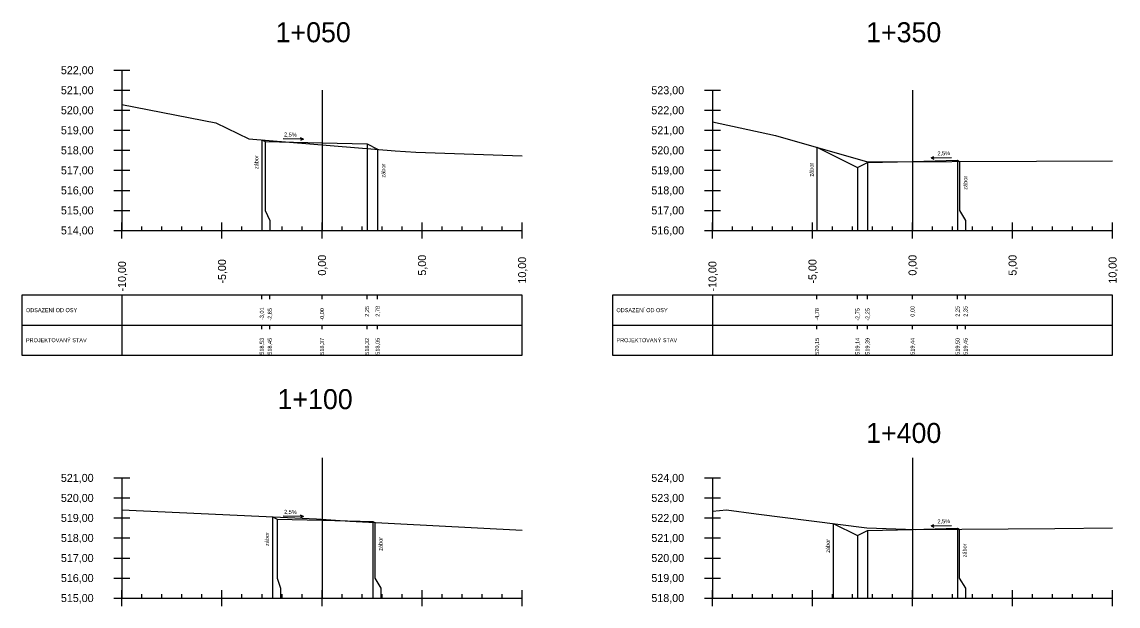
# Model space of a CAD drawing. Extents: x -631407 to -631215, y -1089700 to -1088598.
# Drawn here: x -631314.7 to -631259.9, y -1089386.7 to -1089357.5 of the extents above; entities that cross this region are included whole.
import ezdxf

# ---------------------------------------------------------------- set-up
doc = ezdxf.new("R2010")
doc.units = 0
for name, color, linetype in [('59', 7, 'Continuous'), ('NIVELETA_VYSKY', 7, 'Continuous'), ('REZ_BODY', 7, 'Continuous'), ('REZ_ODSTUPY', 7, 'Continuous'), ('REZ_POPIS', 7, 'Continuous'), ('REZ_RAMY', 7, 'Continuous'), ('REZ_STANICENI', 7, 'Continuous'), ('REZ_SVISLE', 7, 'Continuous'), ('REZ_TENKA', 7, 'Continuous'), ('REZ_TLUSTA', 7, 'Continuous'), ('TABULKA_POPIS', 7, 'Continuous'), ('TEREN', 7, 'Continuous'), ('zábor', 7, 'Continuous')]:
    doc.layers.add(name, color=color, linetype=linetype)

msp = doc.modelspace()

# ---------------------------------------------------------------- linework, layer by layer
at = {"layer": '59'}
for p, q in [((-631310.116, -1089359.911), (-631309.316, -1089359.911)), ((-631309.716, -1089359.911), (-631309.716, -1089367.911)), ((-631310.116, -1089360.911), (-631309.316, -1089360.911)), ((-631280.602, -1089360.911), (-631279.802, -1089360.911)), ((-631280.202, -1089360.911), (-631280.202, -1089367.911)), ((-631310.116, -1089361.911), (-631309.316, -1089361.911)), ((-631280.602, -1089361.911), (-631279.802, -1089361.911)), ((-631310.116, -1089362.911), (-631309.316, -1089362.911)), ((-631280.602, -1089362.911), (-631279.802, -1089362.911)), ((-631310.116, -1089363.911), (-631309.316, -1089363.911)), ((-631280.602, -1089363.911), (-631279.802, -1089363.911)), ((-631310.116, -1089364.911), (-631309.316, -1089364.911)), ((-631280.602, -1089364.911), (-631279.802, -1089364.911)), ((-631310.116, -1089365.911), (-631309.316, -1089365.911)), ((-631280.602, -1089365.911), (-631279.802, -1089365.911)), ((-631310.116, -1089366.911), (-631309.316, -1089366.911)), ((-631280.602, -1089366.911), (-631279.802, -1089366.911)), ((-631310.116, -1089367.911), (-631309.316, -1089367.911)), ((-631280.602, -1089367.911), (-631279.802, -1089367.911)), ((-631310.116, -1089380.273), (-631309.316, -1089380.273)), ((-631309.716, -1089380.273), (-631309.716, -1089386.273)), ((-631280.602, -1089380.273), (-631279.802, -1089380.273)), ((-631280.202, -1089380.273), (-631280.202, -1089386.273)), ((-631310.116, -1089381.273), (-631309.316, -1089381.273)), ((-631280.602, -1089381.273), (-631279.802, -1089381.273)), ((-631310.116, -1089382.273), (-631309.316, -1089382.273)), ((-631280.602, -1089382.273), (-631279.802, -1089382.273)), ((-631310.116, -1089383.273), (-631309.316, -1089383.273)), ((-631280.602, -1089383.273), (-631279.802, -1089383.273)), ((-631310.116, -1089384.273), (-631309.316, -1089384.273)), ((-631280.602, -1089384.273), (-631279.802, -1089384.273)), ((-631310.116, -1089385.273), (-631309.316, -1089385.273)), ((-631280.602, -1089385.273), (-631279.802, -1089385.273)), ((-631310.116, -1089386.273), (-631309.316, -1089386.273)), ((-631280.602, -1089386.273), (-631279.802, -1089386.273))]:
    msp.add_line(p, q, dxfattribs=at)
at = {"layer": 'REZ_RAMY'}
for p, q in [((-631314.716, -1089371.145), (-631314.716, -1089374.145)), ((-631309.716, -1089371.145), (-631309.716, -1089374.145)), ((-631302.726, -1089371.345), (-631302.726, -1089371.145)), ((-631302.326, -1089371.345), (-631302.326, -1089371.145)), ((-631299.716, -1089371.345), (-631299.716, -1089371.145)), ((-631297.466, -1089371.345), (-631297.466, -1089371.145)), ((-631296.937, -1089371.345), (-631296.937, -1089371.145)), ((-631285.202, -1089371.145), (-631285.202, -1089374.145)), ((-631280.202, -1089371.145), (-631280.202, -1089374.145)), ((-631274.978, -1089371.345), (-631274.978, -1089371.145)), ((-631272.952, -1089371.345), (-631272.952, -1089371.145)), ((-631272.452, -1089371.345), (-631272.452, -1089371.145)), ((-631270.202, -1089371.345), (-631270.202, -1089371.145)), ((-631267.952, -1089371.345), (-631267.952, -1089371.145)), ((-631267.552, -1089371.345), (-631267.552, -1089371.145)), ((-631314.716, -1089372.645), (-631289.716, -1089372.645)), ((-631302.726, -1089372.845), (-631302.726, -1089372.645)), ((-631302.326, -1089372.845), (-631302.326, -1089372.645)), ((-631299.716, -1089372.845), (-631299.716, -1089372.645)), ((-631297.466, -1089372.845), (-631297.466, -1089372.645)), ((-631296.937, -1089372.845), (-631296.937, -1089372.645)), ((-631285.202, -1089372.645), (-631260.202, -1089372.645)), ((-631274.978, -1089372.845), (-631274.978, -1089372.645)), ((-631272.952, -1089372.845), (-631272.952, -1089372.645)), ((-631272.452, -1089372.845), (-631272.452, -1089372.645)), ((-631270.202, -1089372.845), (-631270.202, -1089372.645)), ((-631267.952, -1089372.845), (-631267.952, -1089372.645)), ((-631267.552, -1089372.845), (-631267.552, -1089372.645))]:
    msp.add_line(p, q, dxfattribs=at)
for points in [[(-631314.716, -1089371.145), (-631314.716, -1089374.145), (-631289.716, -1089374.145), (-631289.716, -1089371.145)], [(-631285.202, -1089371.145), (-631285.202, -1089374.145), (-631260.202, -1089374.145), (-631260.202, -1089371.145)]]:
    msp.add_lwpolyline(points, close=True, dxfattribs=at)
at = {"layer": 'REZ_SVISLE'}
for points in [[(-631302.726, -1089363.386), (-631302.726, -1089366.911), (-631302.726, -1089367.411), (-631302.726, -1089367.911)], [(-631302.566, -1089363.466), (-631302.566, -1089366.911), (-631302.326, -1089367.411), (-631302.326, -1089367.911)], [(-631299.716, -1089363.537), (-631299.716, -1089366.911), (-631299.716, -1089367.411), (-631299.716, -1089367.911)], [(-631297.466, -1089363.594), (-631297.466, -1089366.911), (-631297.466, -1089367.411), (-631297.466, -1089367.911)], [(-631274.978, -1089363.761), (-631274.978, -1089366.911), (-631274.978, -1089367.411), (-631274.978, -1089367.911)], [(-631296.937, -1089363.858), (-631296.937, -1089366.911), (-631296.937, -1089367.411), (-631296.937, -1089367.911)], [(-631272.952, -1089364.774), (-631272.952, -1089366.911), (-631272.952, -1089367.411), (-631272.952, -1089367.911)], [(-631272.452, -1089364.524), (-631272.452, -1089366.911), (-631272.452, -1089367.411), (-631272.452, -1089367.911)], [(-631270.202, -1089364.467), (-631270.202, -1089366.911), (-631270.202, -1089367.411), (-631270.202, -1089367.911)], [(-631267.952, -1089364.411), (-631267.952, -1089366.911), (-631267.952, -1089367.411), (-631267.952, -1089367.911)], [(-631267.849, -1089364.463), (-631267.849, -1089366.911), (-631267.552, -1089367.411), (-631267.552, -1089367.911)], [(-631302.196, -1089382.211), (-631302.196, -1089385.273), (-631302.196, -1089385.773), (-631302.196, -1089386.273)], [(-631301.966, -1089382.326), (-631301.966, -1089385.273), (-631301.796, -1089385.773), (-631301.796, -1089386.273)], [(-631299.716, -1089382.383), (-631299.716, -1089385.273), (-631299.716, -1089385.773), (-631299.716, -1089386.273)], [(-631297.173, -1089382.446), (-631297.173, -1089385.273), (-631297.173, -1089385.773), (-631297.173, -1089386.273)], [(-631297.074, -1089382.496), (-631297.074, -1089385.273), (-631296.773, -1089385.773), (-631296.773, -1089386.273)], [(-631274.164, -1089382.546), (-631274.164, -1089385.273), (-631274.164, -1089385.773), (-631274.164, -1089386.273)], [(-631272.452, -1089382.903), (-631272.452, -1089385.273), (-631272.452, -1089385.773), (-631272.452, -1089386.273)], [(-631270.202, -1089382.846), (-631270.202, -1089385.273), (-631270.202, -1089385.773), (-631270.202, -1089386.273)], [(-631267.952, -1089382.79), (-631267.952, -1089385.273), (-631267.952, -1089385.773), (-631267.952, -1089386.273)], [(-631267.878, -1089382.827), (-631267.878, -1089385.273), (-631267.552, -1089385.773), (-631267.552, -1089386.273)], [(-631272.952, -1089383.153), (-631272.952, -1089385.273), (-631272.952, -1089385.773), (-631272.952, -1089386.273)]]:
    msp.add_lwpolyline(points, dxfattribs=at)
at = {"layer": 'REZ_TENKA'}
for p, q in [((-631308.716, -1089367.911), (-631308.716, -1089367.711)), ((-631307.716, -1089367.911), (-631307.716, -1089367.711)), ((-631306.716, -1089367.911), (-631306.716, -1089367.711)), ((-631305.716, -1089367.911), (-631305.716, -1089367.711)), ((-631303.716, -1089367.911), (-631303.716, -1089367.711)), ((-631302.716, -1089367.911), (-631302.716, -1089367.711)), ((-631301.716, -1089367.911), (-631301.716, -1089367.711)), ((-631300.716, -1089367.911), (-631300.716, -1089367.711)), ((-631298.716, -1089367.911), (-631298.716, -1089367.711)), ((-631297.716, -1089367.911), (-631297.716, -1089367.711)), ((-631296.716, -1089367.911), (-631296.716, -1089367.711)), ((-631295.716, -1089367.911), (-631295.716, -1089367.711)), ((-631293.716, -1089367.911), (-631293.716, -1089367.711)), ((-631292.716, -1089367.911), (-631292.716, -1089367.711)), ((-631291.716, -1089367.911), (-631291.716, -1089367.711)), ((-631290.716, -1089367.911), (-631290.716, -1089367.711)), ((-631279.202, -1089367.911), (-631279.202, -1089367.711)), ((-631278.202, -1089367.911), (-631278.202, -1089367.711)), ((-631277.202, -1089367.911), (-631277.202, -1089367.711)), ((-631276.202, -1089367.911), (-631276.202, -1089367.711)), ((-631274.202, -1089367.911), (-631274.202, -1089367.711)), ((-631273.202, -1089367.911), (-631273.202, -1089367.711)), ((-631272.202, -1089367.911), (-631272.202, -1089367.711)), ((-631271.202, -1089367.911), (-631271.202, -1089367.711)), ((-631269.202, -1089367.911), (-631269.202, -1089367.711)), ((-631268.202, -1089367.911), (-631268.202, -1089367.711)), ((-631267.202, -1089367.911), (-631267.202, -1089367.711)), ((-631266.202, -1089367.911), (-631266.202, -1089367.711)), ((-631264.202, -1089367.911), (-631264.202, -1089367.711)), ((-631263.202, -1089367.911), (-631263.202, -1089367.711)), ((-631262.202, -1089367.911), (-631262.202, -1089367.711)), ((-631261.202, -1089367.911), (-631261.202, -1089367.711)), ((-631308.716, -1089386.273), (-631308.716, -1089386.073)), ((-631307.716, -1089386.273), (-631307.716, -1089386.073)), ((-631306.716, -1089386.273), (-631306.716, -1089386.073)), ((-631305.716, -1089386.273), (-631305.716, -1089386.073)), ((-631303.716, -1089386.273), (-631303.716, -1089386.073)), ((-631302.716, -1089386.273), (-631302.716, -1089386.073)), ((-631301.716, -1089386.273), (-631301.716, -1089386.073)), ((-631300.716, -1089386.273), (-631300.716, -1089386.073)), ((-631298.716, -1089386.273), (-631298.716, -1089386.073)), ((-631297.716, -1089386.273), (-631297.716, -1089386.073)), ((-631296.716, -1089386.273), (-631296.716, -1089386.073)), ((-631295.716, -1089386.273), (-631295.716, -1089386.073)), ((-631293.716, -1089386.273), (-631293.716, -1089386.073)), ((-631292.716, -1089386.273), (-631292.716, -1089386.073)), ((-631291.716, -1089386.273), (-631291.716, -1089386.073)), ((-631290.716, -1089386.273), (-631290.716, -1089386.073)), ((-631279.202, -1089386.273), (-631279.202, -1089386.073)), ((-631278.202, -1089386.273), (-631278.202, -1089386.073)), ((-631277.202, -1089386.273), (-631277.202, -1089386.073)), ((-631276.202, -1089386.273), (-631276.202, -1089386.073)), ((-631274.202, -1089386.273), (-631274.202, -1089386.073)), ((-631273.202, -1089386.273), (-631273.202, -1089386.073)), ((-631272.202, -1089386.273), (-631272.202, -1089386.073)), ((-631271.202, -1089386.273), (-631271.202, -1089386.073)), ((-631269.202, -1089386.273), (-631269.202, -1089386.073)), ((-631268.202, -1089386.273), (-631268.202, -1089386.073)), ((-631267.202, -1089386.273), (-631267.202, -1089386.073)), ((-631266.202, -1089386.273), (-631266.202, -1089386.073)), ((-631264.202, -1089386.273), (-631264.202, -1089386.073)), ((-631263.202, -1089386.273), (-631263.202, -1089386.073)), ((-631262.202, -1089386.273), (-631262.202, -1089386.073)), ((-631261.202, -1089386.273), (-631261.202, -1089386.073))]:
    msp.add_line(p, q, dxfattribs=at)
at = {"layer": 'REZ_TLUSTA'}
for p, q in [((-631299.716, -1089360.911), (-631299.716, -1089367.911)), ((-631270.202, -1089360.911), (-631270.202, -1089367.911)), ((-631309.716, -1089368.311), (-631309.716, -1089367.511)), ((-631304.716, -1089368.311), (-631304.716, -1089367.511)), ((-631299.716, -1089368.311), (-631299.716, -1089367.511)), ((-631294.716, -1089368.311), (-631294.716, -1089367.511)), ((-631289.716, -1089368.311), (-631289.716, -1089367.511)), ((-631280.202, -1089368.311), (-631280.202, -1089367.511)), ((-631275.202, -1089368.311), (-631275.202, -1089367.511)), ((-631270.202, -1089368.311), (-631270.202, -1089367.511)), ((-631265.202, -1089368.311), (-631265.202, -1089367.511)), ((-631260.202, -1089368.311), (-631260.202, -1089367.511)), ((-631309.716, -1089367.911), (-631289.716, -1089367.911)), ((-631280.202, -1089367.911), (-631260.202, -1089367.911)), ((-631299.716, -1089379.273), (-631299.716, -1089386.273)), ((-631270.202, -1089379.273), (-631270.202, -1089386.273)), ((-631309.716, -1089386.673), (-631309.716, -1089385.873)), ((-631309.716, -1089386.273), (-631289.716, -1089386.273)), ((-631304.716, -1089386.673), (-631304.716, -1089385.873)), ((-631299.716, -1089386.673), (-631299.716, -1089385.873)), ((-631294.716, -1089386.673), (-631294.716, -1089385.873)), ((-631289.716, -1089386.673), (-631289.716, -1089385.873)), ((-631280.202, -1089386.673), (-631280.202, -1089385.873)), ((-631280.202, -1089386.273), (-631260.202, -1089386.273)), ((-631275.202, -1089386.673), (-631275.202, -1089385.873)), ((-631270.202, -1089386.673), (-631270.202, -1089385.873)), ((-631265.202, -1089386.673), (-631265.202, -1089385.873)), ((-631260.202, -1089386.673), (-631260.202, -1089385.873))]:
    msp.add_line(p, q, dxfattribs=at)
at = {"layer": 'TEREN'}
for points in [[(-631309.716, -1089361.631), (-631305.031, -1089362.537), (-631303.379, -1089363.332), (-631296.061, -1089363.929), (-631295.03, -1089364.005), (-631289.716, -1089364.187)], [(-631280.202, -1089362.497), (-631277.056, -1089363.166), (-631272.457, -1089364.482), (-631264.01, -1089364.447), (-631260.202, -1089364.43)], [(-631302.726, -1089363.386), (-631302.566, -1089363.466), (-631299.716, -1089363.537), (-631297.466, -1089363.594), (-631296.937, -1089363.858)], [(-631274.978, -1089363.761), (-631272.952, -1089364.774), (-631272.452, -1089364.524), (-631270.202, -1089364.467), (-631267.952, -1089364.411), (-631267.849, -1089364.463)], [(-631309.716, -1089381.868), (-631299.996, -1089382.311), (-631298.333, -1089382.429), (-631289.716, -1089382.886)], [(-631280.202, -1089381.931), (-631279.505, -1089381.861), (-631278.009, -1089382.061), (-631272.489, -1089382.758), (-631270.074, -1089382.842), (-631263.083, -1089382.795), (-631260.202, -1089382.77)], [(-631302.196, -1089382.211), (-631301.966, -1089382.326), (-631299.716, -1089382.383), (-631297.173, -1089382.446), (-631297.074, -1089382.496)], [(-631274.164, -1089382.546), (-631272.952, -1089383.153), (-631272.452, -1089382.903), (-631270.202, -1089382.846), (-631267.952, -1089382.79), (-631267.878, -1089382.827)]]:
    msp.add_lwpolyline(points, dxfattribs=at)
at = {"layer": 'zábor'}
for p, q in [((-631300.649, -1089363.358), (-631300.785, -1089363.293)), ((-631300.649, -1089363.358), (-631301.657, -1089363.332)), ((-631300.649, -1089363.358), (-631300.788, -1089363.415)), ((-631269.269, -1089364.288), (-631269.132, -1089364.223)), ((-631269.269, -1089364.288), (-631268.261, -1089364.263)), ((-631269.269, -1089364.288), (-631269.129, -1089364.346)), ((-631300.649, -1089382.203), (-631301.657, -1089382.178)), ((-631300.649, -1089382.203), (-631300.788, -1089382.261)), ((-631300.649, -1089382.203), (-631300.785, -1089382.139)), ((-631269.269, -1089382.667), (-631269.132, -1089382.602)), ((-631269.269, -1089382.667), (-631268.261, -1089382.642)), ((-631269.269, -1089382.667), (-631269.129, -1089382.725))]:
    msp.add_line(p, q, dxfattribs=at)

# ---------------------------------------------------------------- texts
at = {"layer": 'NIVELETA_VYSKY'}
for s, p in [('518,53', (-631302.626, -1089374.121)), ('518,45', (-631302.226, -1089374.121)), ('518,37', (-631299.616, -1089374.121)), ('518,32', (-631297.366, -1089374.121)), ('518,05', (-631296.837, -1089374.121)), ('520,15', (-631274.878, -1089374.121)), ('519,14', (-631272.852, -1089374.121)), ('519,39', (-631272.352, -1089374.121)), ('519,44', (-631270.102, -1089374.121)), ('519,50', (-631267.852, -1089374.121)), ('519,45', (-631267.452, -1089374.121))]:
    msp.add_text(s, height=0.2, rotation=90, dxfattribs=at).set_placement(p)
at = {"layer": 'REZ_BODY'}
for s, p in [('-3,01', (-631302.626, -1089372.389)), ('-2,85', (-631302.226, -1089372.422)), ('-0,00', (-631299.616, -1089372.422)), ('2,25', (-631297.366, -1089372.224)), ('2,78', (-631296.837, -1089372.224)), ('-4,78', (-631274.878, -1089372.422)), ('-2,75', (-631272.852, -1089372.422)), ('-2,25', (-631272.352, -1089372.422)), ('0,00', (-631270.102, -1089372.224)), ('2,25', (-631267.852, -1089372.224)), ('2,35', (-631267.452, -1089372.224))]:
    msp.add_text(s, height=0.2, rotation=90, dxfattribs=at).set_placement(p)
at = {"layer": 'REZ_ODSTUPY'}
for s, p in [('0,00', (-631299.516, -1089370.17)), ('5,00', (-631294.516, -1089370.17)), ('10,00', (-631289.516, -1089370.567)), ('0,00', (-631270.002, -1089370.17)), ('5,00', (-631265.002, -1089370.17)), ('10,00', (-631260.002, -1089370.567)), ('-10,00', (-631309.516, -1089370.963)), ('-5,00', (-631304.516, -1089370.567)), ('-10,00', (-631280.002, -1089370.963)), ('-5,00', (-631275.002, -1089370.567))]:
    msp.add_text(s, height=0.4, rotation=90, dxfattribs=at).set_placement(p)
at = {"layer": 'REZ_POPIS'}
for s, p in [('522,00', (-631312.768, -1089360.111)), ('521,00', (-631312.768, -1089361.111)), ('523,00', (-631283.254, -1089361.111)), ('520,00', (-631312.768, -1089362.111)), ('522,00', (-631283.254, -1089362.111)), ('519,00', (-631312.768, -1089363.111)), ('521,00', (-631283.254, -1089363.111)), ('518,00', (-631312.768, -1089364.111)), ('520,00', (-631283.254, -1089364.111)), ('517,00', (-631312.768, -1089365.111)), ('519,00', (-631283.254, -1089365.111)), ('516,00', (-631312.768, -1089366.111)), ('518,00', (-631283.254, -1089366.111)), ('515,00', (-631312.768, -1089367.111)), ('517,00', (-631283.254, -1089367.111)), ('514,00', (-631312.768, -1089368.111)), ('516,00', (-631283.254, -1089368.111)), ('521,00', (-631312.768, -1089380.473)), ('524,00', (-631283.254, -1089380.473)), ('520,00', (-631312.768, -1089381.473)), ('523,00', (-631283.254, -1089381.473)), ('519,00', (-631312.768, -1089382.473)), ('522,00', (-631283.254, -1089382.473)), ('518,00', (-631312.768, -1089383.473)), ('521,00', (-631283.254, -1089383.473)), ('517,00', (-631312.768, -1089384.473)), ('520,00', (-631283.254, -1089384.473)), ('516,00', (-631312.768, -1089385.473)), ('519,00', (-631283.254, -1089385.473)), ('515,00', (-631312.768, -1089386.473)), ('518,00', (-631283.254, -1089386.473))]:
    msp.add_text(s, height=0.4, dxfattribs=at).set_placement(p)
at = {"layer": 'REZ_STANICENI'}
for s, p in [('1+050', (-631302.035, -1089358.515)), ('1+350', (-631272.52, -1089358.515)), ('1+100', (-631301.939, -1089376.839)), ('1+400', (-631272.52, -1089378.528))]:
    msp.add_text(s, height=1, dxfattribs=at).set_placement(p)
at = {"layer": 'TABULKA_POPIS'}
for s, p in [('ODSAZENÍ OD OSY', (-631314.516, -1089371.995)), ('ODSAZENÍ OD OSY', (-631285.002, -1089371.995)), ('PROJEKTOVANÝ STAV', (-631314.516, -1089373.495)), ('PROJEKTOVANÝ STAV', (-631285.002, -1089373.495))]:
    msp.add_text(s, height=0.2, dxfattribs=at).set_placement(p)
at = {"layer": 'zábor'}
for s, rotation, p in [('2,5%', 358.5679, (-631301.613, -1089363.221)), ('zábor', 90, (-631302.897, -1089364.849)), ('2,5%', 1.4321, (-631268.952, -1089364.167)), ('zábor', 90, (-631296.554, -1089365.272)), ('zábor', 90, (-631275.148, -1089365.224)), ('zábor', 90, (-631267.466, -1089365.877)), ('2,5%', 358.5679, (-631301.613, -1089382.066)), ('2,5%', 1.4321, (-631268.952, -1089382.546)), ('zábor', 90, (-631302.366, -1089383.675)), ('zábor', 90, (-631296.691, -1089383.91)), ('zábor', 90, (-631274.334, -1089384.01)), ('zábor', 90, (-631267.495, -1089384.241))]:
    msp.add_text(s, height=0.2, rotation=rotation, dxfattribs=at).set_placement(p)

doc.saveas('drawing.dxf')
